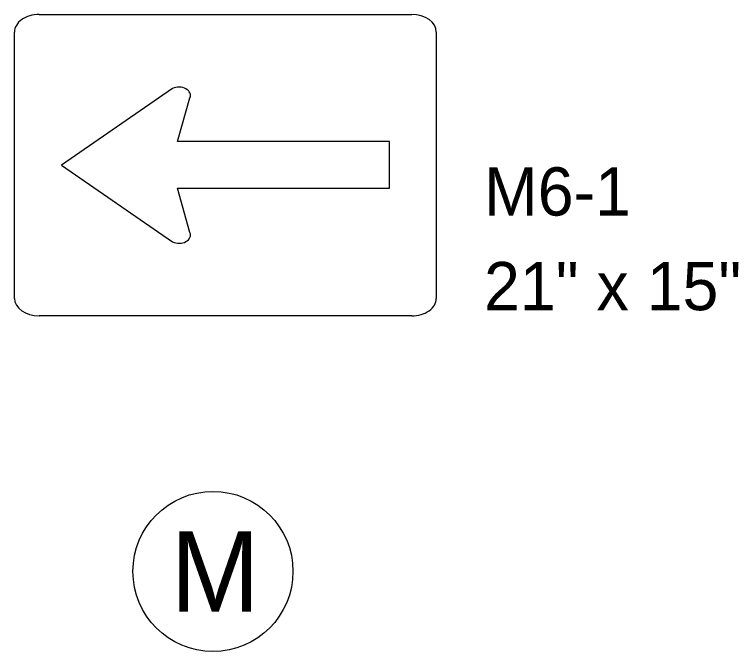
# Model space of a CAD drawing. Extents: x 2157572 to 5059327, y 715220 to 1674494.
# Drawn here: x 2165533.5 to 2165971.8, y 729305.6 to 729690.9 of the extents above; entities that cross this region are included whole.
import ezdxf

# ---------------------------------------------------------------- set-up
doc = ezdxf.new("R2010")
doc.units = 0
for name, color, linetype in [('Exist Cultural Church Label', 7, 'Continuous'), ('Level 57', 7, 'Continuous'), ('Map Preparation County Base Legend Highway Garage or Maintenance Office', 7, 'Continuous')]:
    doc.layers.add(name, color=color, linetype=linetype)

msp = doc.modelspace()

# ---------------------------------------------------------------- linework, layer by layer
at = {"layer": 'Exist Cultural Church Label'}
msp.add_circle((2165653.66, 729354.01), 48.43, dxfattribs=at)
at = {"layer": 'Level 57'}
for p, q in [((2165661.18, 729690.93), (2165661.18, 729690.93)), ((2165629.22, 729646.08), (2165561.94, 729599.75)), ((2165632.14, 729614.03), (2165639.74, 729640.44)), ((2165760.56, 729614.03), (2165632.14, 729614.03)), ((2165760.56, 729585.94), (2165760.56, 729614.03)), ((2165561.94, 729599.75), (2165629.22, 729553.41)), ((2165632.16, 729585.93), (2165760.56, 729585.94)), ((2165639.73, 729559.05), (2165632.16, 729585.93))]:
    msp.add_line(p, q, dxfattribs=at)
for points in [[(2165548.41, 729690.93), (2165773.94, 729690.93)], [(2165533.51, 729519.19), (2165533.51, 729680.29)], [(2165788.83, 729680.29), (2165788.83, 729519.2)], [(2165773.94, 729508.56), (2165548.41, 729508.56)]]:
    msp.add_lwpolyline(points, dxfattribs=at)
for centre, major_axis, ratio, start_param, end_param in [((2165548.41, 729680.29), (-14.89, 0), 0.714286, 4.712162, 6.283185), ((2165773.94, 729680.29), (14.89, 0), 0.714286, 0, 1.570796), ((2165633.14, 729641.97), (-6.93, 0), 0.720018, 2.830616, 5.313575), ((2165633.14, 729557.52), (-6.93, 0), 0.720018, 0.969609, 3.452568), ((2165548.41, 729519.2), (-14.89, 0), 0.714286, 0, 1.570796), ((2165773.94, 729519.2), (-14.89, 0), 0.714286, 1.570796, 3.141593)]:
    msp.add_ellipse(centre, major_axis=major_axis, ratio=ratio, start_param=start_param, end_param=end_param, dxfattribs=at)
at = {"layer": 'Map Preparation County Base Legend Highway Garage or Maintenance Office'}
msp.add_circle((2165653.66, 729354.01), 48.43, dxfattribs=at)

# ---------------------------------------------------------------- texts
at = {"layer": 'Exist Cultural Church Label'}
msp.add_text('M', height=48.63, dxfattribs=at).set_placement((2165627.91, 729329.69))
at = {"layer": 'Level 57'}
for s, p in [('M6-1', (2165817.74, 729569.3)), ('21" x 15"', (2165817.74, 729512.04))]:
    msp.add_text(s, height=29.18, rotation=360, dxfattribs=at).set_placement(p)

doc.saveas('drawing.dxf')
